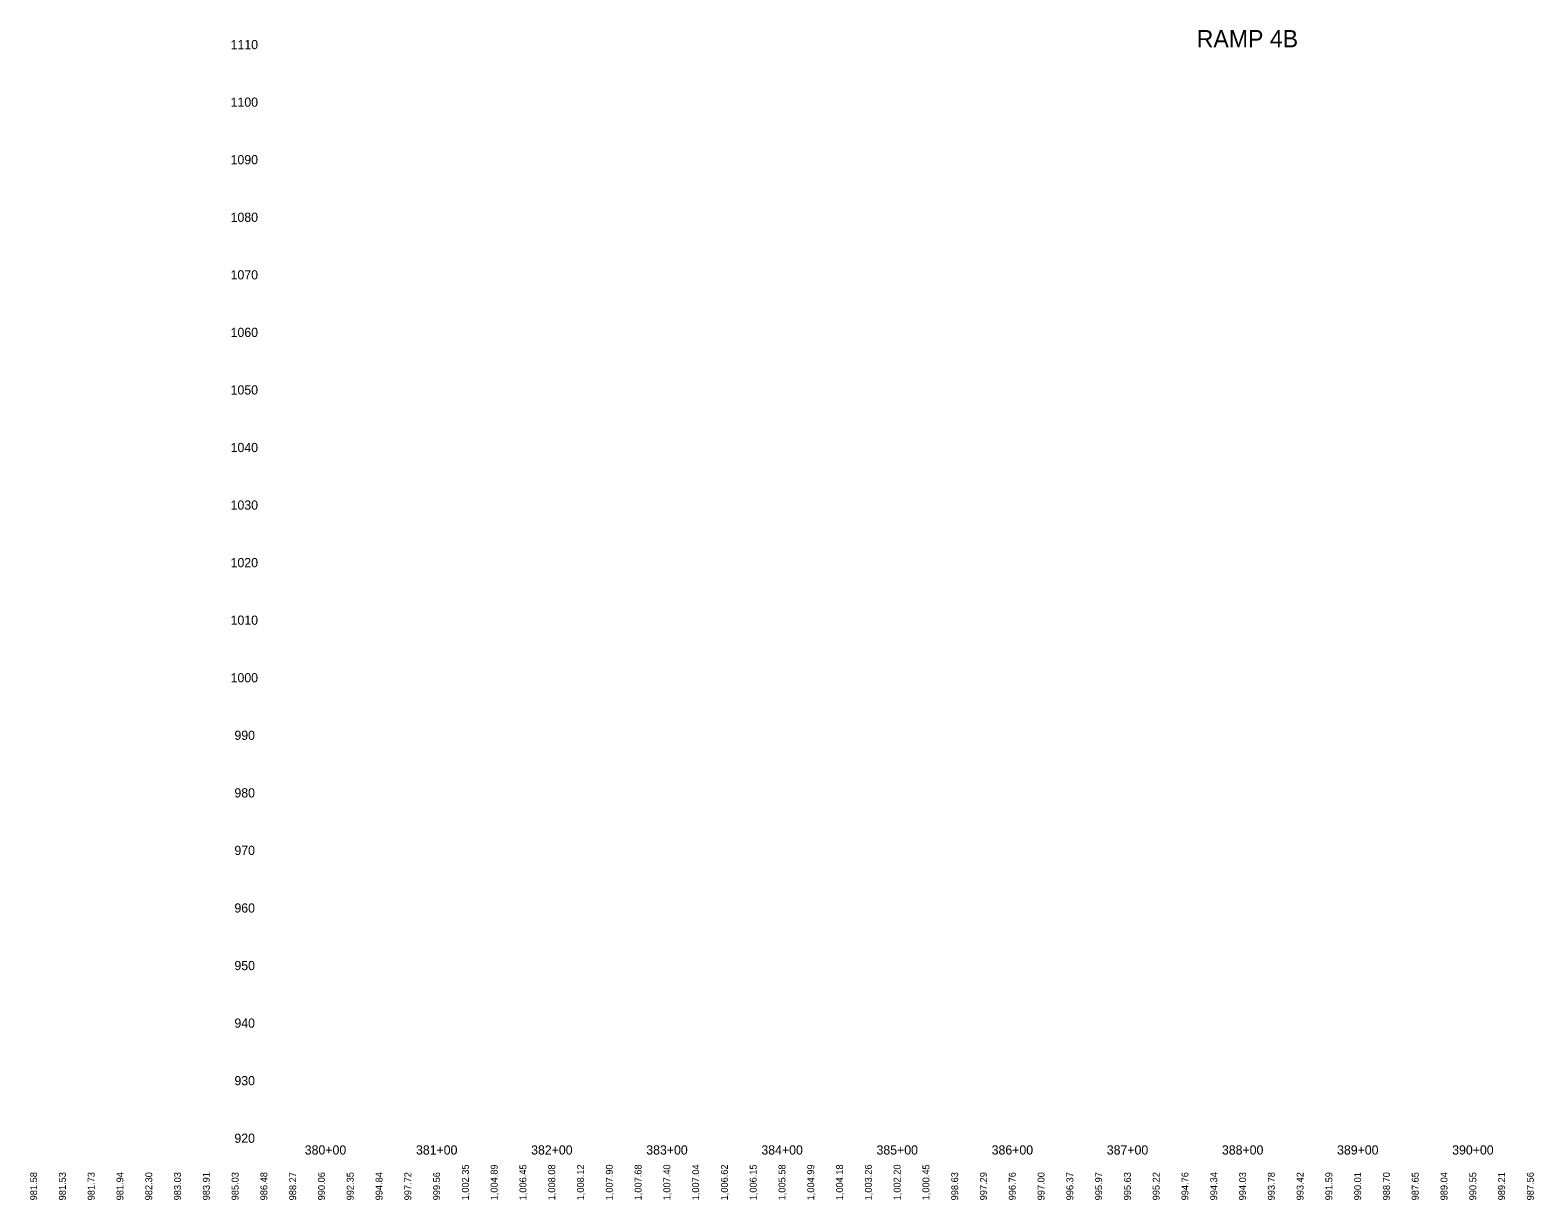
# Model space of a CAD drawing. Extents: x 16972137 to 16976737, y 12558490 to 12559551.
# Drawn here: x 16972137 to 16973443, y 12558490 to 12559506 of the extents above; entities that cross this region are included whole.
import ezdxf

# ---------------------------------------------------------------- set-up
doc = ezdxf.new("R2010")
doc.units = 0
for name, color, linetype in [('RD_DDB_ElevTX', 7, 'Continuous'), ('RD_DDB_StaTX', 7, 'Continuous'), ('RD_DDB_StripGrade_PR', 7, 'Continuous'), ('RD_SHT_TX', 7, 'Continuous')]:
    doc.layers.add(name, color=color, linetype=linetype)

msp = doc.modelspace()

# ---------------------------------------------------------------- texts
at = {"layer": 'RD_DDB_ElevTX'}
for s, p in [('1110', (16972311, 12559489.3)), ('1100', (16972311, 12559439.3)), ('1090', (16972311, 12559389.3)), ('1080', (16972311, 12559339.3)), ('1070', (16972311, 12559289.3)), ('1060', (16972311, 12559239.3)), ('1050', (16972311, 12559189.3)), ('1040', (16972311, 12559139.3)), ('1030', (16972311, 12559089.3)), ('1020', (16972311, 12559039.3)), ('1010', (16972311, 12558989.3)), ('1000', (16972311, 12558939.3)), ('990', (16972314.3, 12558889.3)), ('980', (16972314.3, 12558839.3)), ('970', (16972314.3, 12558789.3)), ('960', (16972314.3, 12558739.3)), ('950', (16972314.3, 12558689.3)), ('940', (16972314.3, 12558639.3)), ('930', (16972314.3, 12558589.3)), ('920', (16972314.3, 12558539.3))]:
    msp.add_text(s, height=8, dxfattribs=at).set_placement(p)
at = {"layer": 'RD_DDB_StaTX'}
for s, p in [('380+00', (16972375.4, 12558529.1)), ('381+00', (16972472, 12558529.1)), ('382+00', (16972572, 12558529.1)), ('383+00', (16972672, 12558529.1)), ('384+00', (16972772, 12558529.1)), ('385+00', (16972872, 12558529.1)), ('386+00', (16972972, 12558529.1)), ('387+00', (16973072, 12558529.1)), ('388+00', (16973172, 12558529.1)), ('389+00', (16973272, 12558529.1)), ('390+00', (16973372, 12558529.1))]:
    msp.add_text(s, height=8, dxfattribs=at).set_placement(p)
at = {"layer": 'RD_DDB_StripGrade_PR'}
for s, p in [('1,002.35', (16972517.9, 12558489.3)), ('1,004.89', (16972542.9, 12558489.3)), ('1,006.45', (16972567.9, 12558489.3)), ('1,008.08', (16972592.9, 12558489.3)), ('1,008.12', (16972617.9, 12558489.3)), ('1,007.90', (16972642.9, 12558489.3)), ('1,007.68', (16972667.9, 12558489.3)), ('1,007.40', (16972692.9, 12558489.3)), ('1,007.04', (16972717.9, 12558489.3)), ('1,006.62', (16972742.9, 12558489.3)), ('1,006.15', (16972767.9, 12558489.3)), ('1,005.58', (16972792.9, 12558489.3)), ('1,004.99', (16972817.9, 12558489.3)), ('1,004.18', (16972842.9, 12558489.3)), ('1,003.26', (16972867.9, 12558489.3)), ('1,002.20', (16972892.9, 12558489.3)), ('1,000.45', (16972917.9, 12558489.3)), ('981.58', (16972142.9, 12558489.3)), ('981.53', (16972167.9, 12558489.3)), ('981.73', (16972192.9, 12558489.3)), ('981.94', (16972217.9, 12558489.3)), ('982.30', (16972242.9, 12558489.3)), ('983.03', (16972267.9, 12558489.3)), ('983.91', (16972292.9, 12558489.3)), ('985.03', (16972317.9, 12558489.3)), ('986.48', (16972342.9, 12558489.3)), ('988.27', (16972367.9, 12558489.3)), ('990.06', (16972392.9, 12558489.3)), ('992.35', (16972417.9, 12558489.3)), ('994.84', (16972442.9, 12558489.3)), ('997.72', (16972467.9, 12558489.3)), ('999.56', (16972492.9, 12558489.3)), ('998.63', (16972942.9, 12558489.3)), ('997.29', (16972967.9, 12558489.3)), ('996.76', (16972992.9, 12558489.3)), ('997.00', (16973017.9, 12558489.3)), ('996.37', (16973042.9, 12558489.3)), ('995.97', (16973067.9, 12558489.3)), ('995.63', (16973092.9, 12558489.3)), ('995.22', (16973117.9, 12558489.3)), ('994.76', (16973142.9, 12558489.3)), ('994.34', (16973167.9, 12558489.3)), ('994.03', (16973192.9, 12558489.3)), ('993.78', (16973217.9, 12558489.3)), ('993.42', (16973242.9, 12558489.3)), ('991.59', (16973267.9, 12558489.3)), ('990.01', (16973292.9, 12558489.3)), ('988.70', (16973317.9, 12558489.3)), ('987.65', (16973342.9, 12558489.3)), ('989.04', (16973367.9, 12558489.3)), ('990.55', (16973392.9, 12558489.3)), ('989.21', (16973417.9, 12558489.3)), ('987.56', (16973442.9, 12558489.3))]:
    msp.add_text(s, height=6, rotation=90, dxfattribs=at).set_placement(p)
at = {"layer": 'RD_SHT_TX'}
msp.add_text('RAMP 4B', height=15, dxfattribs=at).set_placement((16973150.1, 12559490.9))

doc.saveas('drawing.dxf')
